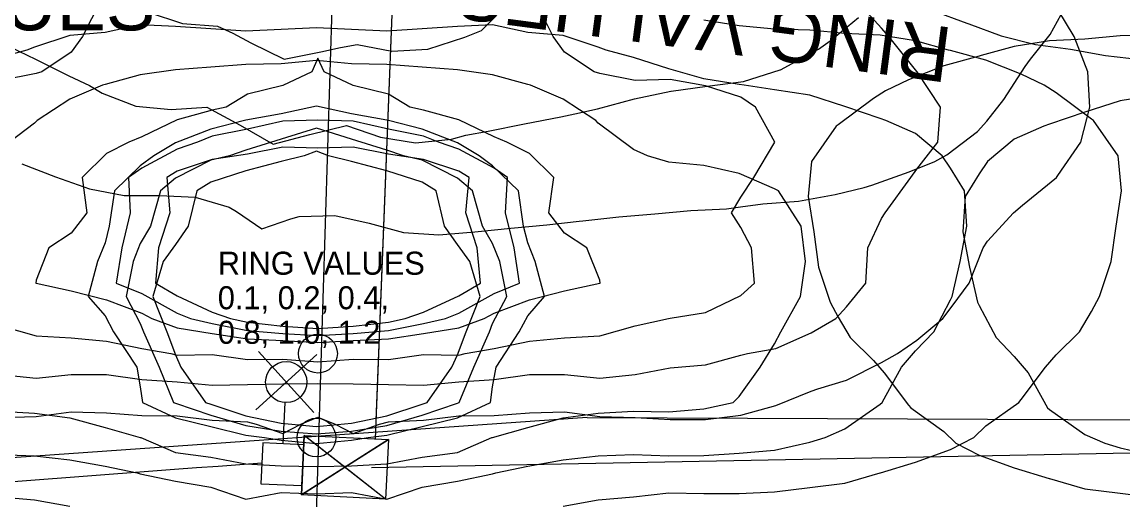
# Model space of a CAD drawing. Extents: x 1638506 to 1658005, y 834807 to 846788.
# Drawn here: x 1642396.4 to 1642635.4, y 842159.5 to 842263.3 of the extents above; entities that cross this region are included whole.
import ezdxf

# ---------------------------------------------------------------- set-up
doc = ezdxf.new("R2010")
doc.units = 0
for name, color, linetype in [('Default', 7, 'Continuous'), ('Old_Level_1', 7, 'Continuous'), ('Old_Level_2', 7, 'Continuous'), ('Scratch_Level_0', 7, 'Continuous')]:
    doc.layers.add(name, color=color, linetype=linetype)

msp = doc.modelspace()

# ---------------------------------------------------------------- linework, layer by layer
at = {"layer": 'Default'}
for p, q in [((1642473.12, 842172.77), (1642480.55, 842360.24)), ((1642473.28, 842176.7), (1642480.22, 842351.8)), ((1642460.38, 842191.09), (1642447.13, 842179.08)), ((1642459.75, 842178.47), (1642447.73, 842191.69)), ((1642453.76, 842185.1), (1642453.76, 842185.1)), ((1642453.12, 842171.7), (1642453.54, 842180.63)), ((1642456.78, 842181.74), (1642456.78, 842181.74)), ((1642475.33, 842159.68), (1642457.68, 842173.5)), ((1642475.95, 842172.63), (1642457.06, 842160.56)), ((1642472.3, 842166.49), (1642741.9, 842171.8))]:
    msp.add_line(p, q, dxfattribs=at)
for points in [[(1642475.33, 842159.68), (1642457.06, 842160.56), (1642457.68, 842173.5), (1642475.95, 842172.63)], [(1642466.5, 842166.59), (1642457.68, 842173.5), (1642457.06, 842160.56)], [(1642457.16, 842162.58), (1642457.58, 842171.48), (1642448.65, 842171.91), (1642448.22, 842163.01)], [(1642466.5, 842166.59), (1642475.95, 842172.63), (1642475.33, 842159.68)]]:
    msp.add_lwpolyline(points, close=True, dxfattribs=at)
msp.add_circle((1642453.75, 842185.07), 4.47, dxfattribs=at)
msp.add_arc((1643863.61, 823017.34), 19202.35, 94.226402, 95.13232, dxfattribs=at)
at = {"layer": 'Old_Level_1'}
for points in [[(1642571.96, 842280.85), (1642572.33, 842280.5), (1642579.46, 842274.19), (1642581.94, 842272.29), (1642586.72, 842269.48), (1642594.08, 842265.78), (1642601.52, 842263.03), (1642601.94, 842262.86), (1642608.96, 842260.27), (1642616.47, 842258.37), (1642624.06, 842257.35), (1642631.62, 842255.97), (1642639.22, 842255.09)], [(1642601.03, 842226.57), (1642598.01, 842231.5), (1642596.16, 842234.22), (1642590.36, 842239.01), (1642583.95, 842241.87), (1642582.71, 842242.29), (1642575.06, 842244.89), (1642567.41, 842247.34), (1642559.76, 842248.56), (1642553.22, 842249.52), (1642552.11, 842249.71), (1642544.46, 842250.88), (1642536.81, 842253.06), (1642529.16, 842255.54), (1642523.23, 842257.17), (1642521.51, 842257.76), (1642513.86, 842260.3), (1642506.21, 842260.98), (1642498.56, 842262.63), (1642490.91, 842262.25), (1642483.26, 842261.74), (1642475.61, 842261.29), (1642467.96, 842261.61), (1642460.31, 842262.01), (1642452.66, 842261.61), (1642445.01, 842261.29), (1642437.36, 842261.74), (1642429.71, 842262.25), (1642422.06, 842262.63), (1642414.41, 842260.98), (1642406.76, 842260.3), (1642399.11, 842257.76), (1642397.4, 842257.17), (1642391.46, 842255.54)], [(1642629.01, 842241.87), (1642628.61, 842242.18), (1642620.96, 842247.85), (1642618.32, 842249.52), (1642613.31, 842251.91), (1642605.66, 842254.95), (1642598.01, 842257.04), (1642597.58, 842257.17), (1642590.36, 842259.14), (1642582.71, 842260.38), (1642575.06, 842260.73), (1642567.41, 842261.46), (1642559.76, 842261.67), (1642552.11, 842262.46), (1642544.46, 842263.68)], [(1642642.45, 842260.45), (1642634.8, 842260.24), (1642627.15, 842259.51), (1642619.5, 842259.16), (1642611.85, 842257.92), (1642604.64, 842255.95), (1642604.2, 842255.82), (1642596.55, 842253.73), (1642588.9, 842250.69), (1642583.89, 842248.3), (1642581.25, 842246.63), (1642573.6, 842240.96), (1642573.2, 842240.65), (1642567.8, 842233), (1642567.06, 842225.35), (1642568.29, 842217.7), (1642569.35, 842210.05), (1642571.85, 842202.4), (1642573.6, 842199.18), (1642576.21, 842194.75), (1642581.25, 842189.77), (1642583.61, 842187.1), (1642588.9, 842180.09), (1642589.41, 842179.45), (1642596.55, 842174.36), (1642599.16, 842171.8), (1642604.2, 842169.17), (1642611.85, 842166.47), (1642619.44, 842164.15), (1642619.5, 842164.13), (1642627.15, 842161.9), (1642634.8, 842160.94), (1642642.45, 842160.02)], [(1642560.63, 842226.57), (1642559.76, 842227.04), (1642552.11, 842230.38), (1642544.46, 842232.1), (1642536.81, 842232.85), (1642532.19, 842234.22), (1642529.16, 842235.55), (1642521.51, 842241.32), (1642520.99, 842241.87), (1642513.86, 842246.51), (1642506.79, 842249.52), (1642506.21, 842249.69), (1642498.56, 842251.82), (1642490.91, 842252.89), (1642483.26, 842253.44), (1642475.61, 842254.02), (1642467.96, 842254.18), (1642460.31, 842254.91), (1642452.66, 842254.18), (1642445.01, 842254.02), (1642437.36, 842253.44), (1642429.71, 842252.89), (1642422.06, 842251.82), (1642414.41, 842249.69), (1642413.84, 842249.52), (1642406.76, 842246.51), (1642399.64, 842241.87), (1642399.11, 842241.32), (1642391.46, 842235.55)], [(1642642.45, 842247.34), (1642634.8, 842246.12), (1642627.15, 842243.67), (1642619.5, 842241.07), (1642618.26, 842240.65), (1642611.85, 842237.79), (1642606.05, 842233), (1642604.2, 842230.28), (1642601.18, 842225.35), (1642600.7, 842217.7), (1642602.14, 842210.05), (1642603.85, 842202.4), (1642604.2, 842201.7), (1642607.88, 842194.75), (1642611.85, 842190.62), (1642614.83, 842187.1), (1642619.04, 842179.45), (1642619.5, 842179.09), (1642627.15, 842173.71), (1642631.48, 842171.8), (1642634.8, 842170.79), (1642642.45, 842169.07)], [(1642507.83, 842211.27), (1642506.21, 842215.27), (1642505.3, 842218.92), (1642504.19, 842226.57), (1642498.56, 842232.02), (1642495.65, 842234.22), (1642490.91, 842237.01), (1642483.26, 842239.96), (1642475.95, 842241.87), (1642475.61, 842241.95), (1642467.96, 842243.3), (1642460.31, 842245.01), (1642452.66, 842243.3), (1642445.01, 842241.95), (1642444.68, 842241.87), (1642437.36, 842239.96), (1642429.71, 842237.01), (1642424.98, 842234.22), (1642422.06, 842232.02), (1642416.44, 842226.57), (1642415.33, 842218.92), (1642414.41, 842215.27), (1642412.79, 842211.27), (1642410.78, 842203.62), (1642414.41, 842199.45), (1642416.28, 842195.97), (1642421.31, 842188.32), (1642422.06, 842184.02), (1642422.51, 842180.67), (1642429.71, 842177.31), (1642437.36, 842175.45), (1642445.01, 842173.54), (1642449.07, 842173.02), (1642452.66, 842172.43), (1642460.31, 842171.75), (1642467.96, 842172.43), (1642471.55, 842173.02), (1642475.61, 842173.54), (1642483.26, 842175.45), (1642490.91, 842177.31), (1642498.12, 842180.67), (1642498.56, 842184.02), (1642499.31, 842188.32), (1642504.34, 842195.97), (1642506.21, 842199.45), (1642509.84, 842203.62), (1642507.83, 842211.27)], [(1642513.86, 842158.12), (1642521.51, 842159.52), (1642529.16, 842160.17), (1642536.81, 842161.01), (1642544.46, 842160.86), (1642552.11, 842160.91), (1642559.76, 842161.24), (1642567.41, 842162.16), (1642575.06, 842163.13), (1642582.71, 842165.36), (1642582.77, 842165.37), (1642590.36, 842167.69), (1642598.01, 842170.4), (1642603.05, 842173.02), (1642605.66, 842175.58), (1642612.81, 842180.67), (1642613.31, 842181.31), (1642618.61, 842188.32), (1642620.96, 842190.99), (1642626.01, 842195.97), (1642628.61, 842200.4), (1642630.36, 842203.62), (1642632.86, 842211.27), (1642633.93, 842218.92), (1642635.15, 842226.57), (1642634.42, 842234.22), (1642629.01, 842241.87)], [(1642500.11, 842211.27), (1642498.56, 842215.14), (1642496.35, 842218.92), (1642494.2, 842226.57), (1642490.91, 842229.35), (1642483.26, 842233.25), (1642479.23, 842234.22), (1642475.61, 842235.42), (1642467.96, 842237.81), (1642460.31, 842240.21), (1642452.66, 842237.81), (1642445.01, 842235.42), (1642441.4, 842234.22), (1642437.36, 842233.25), (1642429.71, 842229.35), (1642426.43, 842226.57), (1642424.27, 842218.92), (1642422.06, 842215.14), (1642420.52, 842211.27), (1642418.98, 842203.62), (1642422.06, 842197.77), (1642422.76, 842195.97), (1642426.14, 842188.32), (1642429.3, 842180.67), (1642429.71, 842180.48), (1642437.36, 842177.87), (1642445.01, 842175.63), (1642452.66, 842174.41), (1642460.31, 842173.81), (1642467.96, 842174.41), (1642475.61, 842175.63), (1642483.26, 842177.87), (1642490.91, 842180.48), (1642491.33, 842180.67), (1642494.48, 842188.32), (1642497.86, 842195.97), (1642498.56, 842197.77), (1642501.65, 842203.62), (1642500.11, 842211.27)], [(1642493.61, 842211.27), (1642490.91, 842214.93), (1642488.14, 842218.92), (1642486.3, 842226.57), (1642483.26, 842228.49), (1642475.61, 842230.95), (1642467.96, 842232.95), (1642462.94, 842234.22), (1642460.31, 842235.18), (1642457.68, 842234.22), (1642452.66, 842232.95), (1642445.01, 842230.95), (1642437.36, 842228.49), (1642434.32, 842226.57), (1642432.49, 842218.92), (1642429.71, 842214.93), (1642427.02, 842211.27), (1642424.78, 842203.62), (1642427.84, 842195.97), (1642429.71, 842190.99), (1642430.9, 842188.32), (1642436.25, 842180.67), (1642437.36, 842180.29), (1642445.01, 842177.72), (1642452.66, 842176.17), (1642460.31, 842175.4), (1642467.96, 842176.17), (1642475.61, 842177.72), (1642483.26, 842180.29), (1642484.38, 842180.67), (1642489.73, 842188.32), (1642490.91, 842190.99), (1642492.79, 842195.97), (1642495.85, 842203.62), (1642493.61, 842211.27)], [(1642391.46, 842169.38), (1642399.11, 842169.08), (1642406.76, 842168.2), (1642414.41, 842166.78), (1642421.36, 842165.37), (1642422.06, 842165.13), (1642429.71, 842163.59), (1642437.36, 842162.24), (1642445.01, 842159.66), (1642452.66, 842161.07), (1642460.31, 842160.78), (1642467.96, 842161.07), (1642475.61, 842159.66), (1642483.26, 842162.24), (1642490.91, 842163.59), (1642498.56, 842165.13), (1642499.27, 842165.37), (1642506.21, 842166.78), (1642513.86, 842168.2), (1642521.51, 842169.08), (1642529.16, 842169.38), (1642536.81, 842169.09), (1642544.46, 842169.1), (1642552.11, 842169.65), (1642559.76, 842170.29), (1642567.41, 842172.01), (1642570.74, 842173.02), (1642575.06, 842174.94), (1642582.71, 842180.31), (1642583.18, 842180.67), (1642587.38, 842188.32), (1642590.36, 842191.85), (1642594.34, 842195.97), (1642598.01, 842202.92), (1642598.36, 842203.62), (1642600.07, 842211.27), (1642601.51, 842218.92), (1642601.03, 842226.57)], [(1642391.46, 842178.77), (1642399.11, 842178.34), (1642406.76, 842177.29), (1642414.41, 842175.24), (1642422.06, 842173.07), (1642422.19, 842173.02), (1642429.71, 842169.8), (1642437.36, 842168.8), (1642445.01, 842167.32), (1642452.66, 842166.91), (1642460.31, 842166.74), (1642467.96, 842166.91), (1642475.61, 842167.32), (1642483.26, 842168.8), (1642490.91, 842169.8), (1642498.43, 842173.02), (1642498.56, 842173.07), (1642506.21, 842175.24), (1642513.86, 842177.29), (1642521.51, 842178.34), (1642529.16, 842178.77), (1642536.81, 842178.63), (1642544.46, 842179.26), (1642550.77, 842180.67), (1642552.11, 842181.95), (1642556.66, 842188.32), (1642559.76, 842193.38), (1642561.13, 842195.97), (1642565.42, 842203.62), (1642566.48, 842211.27), (1642565.56, 842218.92), (1642560.63, 842226.57)], [(1642391.46, 842160.17), (1642399.11, 842159.52), (1642406.76, 842158.12)]]:
    msp.add_lwpolyline(points, dxfattribs=at)
msp.add_circle((1642460.31, 842173.02), 4.21, dxfattribs=at)
at = {"layer": 'Old_Level_2'}
for p, q in [((1642458.82, 842108.44), (1642469.85, 842461.62)), ((1642519.11, 842177.39), (1642217.73, 842156.22)), ((1642519.08, 842177.38), (1642658.6, 842176.81))]:
    msp.add_line(p, q, dxfattribs=at)
at = {"layer": 'Scratch_Level_0'}
for points in [[(1642413.4, 842267.75), (1642409.54, 842260.1), (1642407.09, 842256.7), (1642400.66, 842252.45), (1642399.44, 842252.07), (1642391.79, 842250.56)], [(1642396.33, 842232.45), (1642403.67, 842229.66), (1642411.05, 842227.06), (1642418.57, 842225.57), (1642426.28, 842225.56), (1642433.96, 842225.25), (1642441.38, 842223.04), (1642442.96, 842222.11), (1642448.48, 842218.38), (1642454.78, 842220.55), (1642456.55, 842221.04), (1642464.29, 842221.25), (1642471.79, 842219.57), (1642479.24, 842217.57), (1642486.89, 842217.07), (1642494.69, 842217.67), (1642502.51, 842218.46), (1642510.32, 842219.2), (1642517.34, 842220.03), (1642518.16, 842220.11), (1642525.98, 842220.94), (1642533.79, 842221.62), (1642541.59, 842222.3), (1642549.36, 842222.71), (1642552.41, 842223.12), (1642557.22, 842223.76), (1642565.02, 842224.38), (1642572.92, 842225.83), (1642579.24, 842227.3), (1642580.91, 842227.85), (1642589, 842230.72), (1642594.57, 842233), (1642597.2, 842234.41), (1642603.86, 842239.49), (1642605.89, 842241.76), (1642609.6, 842246.45), (1642614.17, 842253.56), (1642615.37, 842255.2), (1642619.64, 842260.56), (1642623.63, 842267.75)], [(1642555.62, 842244.8), (1642552.44, 842246.95), (1642544.79, 842249.42), (1642537.14, 842250.78), (1642529.49, 842250.56), (1642521.84, 842252.07), (1642520.62, 842252.45), (1642514.19, 842256.7), (1642511.74, 842260.1), (1642507.88, 842267.75)], [(1642590.75, 842252.45), (1642590.69, 842252.53), (1642584.57, 842260.1), (1642583.04, 842261.93), (1642577.64, 842267.75)], [(1642392.06, 842258.65), (1642399.32, 842255.16), (1642406.56, 842251.55), (1642411.02, 842249.47), (1642413.78, 842247.77), (1642421.13, 842244.99), (1642428.75, 842244.27), (1642436.53, 842244.8), (1642443.73, 842240.84), (1642450.9, 842236.7), (1642458.9, 842238.84), (1642466.87, 842240.8), (1642474.25, 842238.27), (1642481.8, 842236.99), (1642489.62, 842237.78), (1642492.72, 842238.7), (1642497.57, 842239.55), (1642505.5, 842241.17), (1642513.41, 842242.66), (1642516.42, 842243.29), (1642521.36, 842244.39), (1642529.36, 842246.59), (1642537.3, 842248.25), (1642537.33, 842248.26), (1642545.16, 842249.33), (1642553.01, 842250.37), (1642561.02, 842252.85), (1642561.05, 842252.87), (1642569.36, 842257.33), (1642571.87, 842259.14), (1642577.98, 842264.21)], [(1642423.81, 842265.36), (1642431.21, 842262.95), (1642438.85, 842262.35), (1642442.17, 842260.8), (1642446.09, 842258.75), (1642453.33, 842255.18), (1642461.26, 842256.76), (1642465.57, 842257.71), (1642469.18, 842258.35), (1642476.71, 842256.95), (1642484.49, 842257.37), (1642492.55, 842259.99), (1642496.16, 842261.4), (1642501.1, 842266.37)], [(1642624.81, 842260.1), (1642621.29, 842265.98)], [(1642391.79, 842177.35), (1642399.44, 842177.6), (1642407.09, 842178.59), (1642414.74, 842178.38), (1642422.39, 842177.83), (1642430.04, 842177.75), (1642437.69, 842176.79), (1642445.34, 842176.41), (1642447.26, 842175.95), (1642452.99, 842173.9), (1642456.9, 842175.95), (1642460.64, 842177.43), (1642464.37, 842175.95), (1642468.29, 842173.9), (1642474.01, 842175.95), (1642475.94, 842176.41), (1642483.59, 842176.79), (1642491.24, 842177.75), (1642498.89, 842177.83), (1642506.54, 842178.38), (1642514.19, 842178.59), (1642521.84, 842177.6), (1642529.49, 842177.35), (1642537.14, 842176.95), (1642544.79, 842176.95), (1642552.44, 842177.92), (1642560.09, 842180.01), (1642567.74, 842183.08), (1642569.15, 842183.6), (1642575.39, 842185.5), (1642583.04, 842189.34), (1642586.45, 842191.25), (1642590.69, 842194.15), (1642596.29, 842198.9), (1642598.34, 842201.58), (1642602.05, 842206.55), (1642605.1, 842214.2), (1642605.99, 842215.65), (1642611.64, 842221.85), (1642613.64, 842223.52), (1642621, 842229.5), (1642621.29, 842229.93), (1642626.32, 842237.15), (1642628.22, 842244.8), (1642627.83, 842252.45), (1642624.81, 842260.1)], [(1642521.92, 842206.55), (1642521.84, 842207.21), (1642519.05, 842214.2), (1642514.19, 842217.39), (1642510.8, 842221.85), (1642511.84, 842229.5), (1642506.54, 842234.69), (1642501.67, 842237.15), (1642498.89, 842238.33), (1642491.24, 842241.98), (1642483.59, 842244.1), (1642480.58, 842244.8), (1642475.94, 842247.61), (1642468.29, 842249.47), (1642461.97, 842252.45), (1642460.64, 842255.38), (1642459.31, 842252.45), (1642452.99, 842249.47), (1642445.34, 842247.61), (1642440.69, 842244.8), (1642437.69, 842244.1), (1642430.04, 842241.98), (1642422.39, 842238.33), (1642419.6, 842237.15), (1642414.74, 842234.69), (1642409.44, 842229.5), (1642410.48, 842221.85), (1642407.09, 842217.39), (1642402.22, 842214.2), (1642399.44, 842207.2), (1642399.35, 842206.55), (1642399.44, 842206.52), (1642407.09, 842204.85), (1642414.74, 842202.95), (1642422.39, 842200.06), (1642424.55, 842198.9), (1642430.04, 842196.88), (1642437.69, 842195.59), (1642445.34, 842194.46), (1642452.99, 842194.07), (1642460.64, 842193.7), (1642468.29, 842194.07), (1642475.94, 842194.46), (1642483.59, 842195.59), (1642491.24, 842196.88), (1642496.72, 842198.9), (1642498.89, 842200.06), (1642506.54, 842202.95), (1642514.19, 842204.85), (1642521.84, 842206.52), (1642521.92, 842206.55)], [(1642391.79, 842186.68), (1642399.44, 842185.94), (1642407.09, 842186.7), (1642414.74, 842186.71), (1642422.39, 842185.6), (1642430.04, 842185.13), (1642437.69, 842184.39), (1642445.34, 842184.51), (1642452.99, 842184.71), (1642460.64, 842184.78), (1642468.29, 842184.71), (1642475.94, 842184.51), (1642483.59, 842184.39), (1642491.24, 842185.13), (1642498.89, 842185.6), (1642506.54, 842186.71), (1642514.19, 842186.7), (1642521.84, 842185.94), (1642529.49, 842186.68), (1642537.14, 842188.14), (1642544.79, 842188.81), (1642552.44, 842190.89), (1642553.89, 842191.25), (1642560.09, 842192.35), (1642567.74, 842195.77), (1642573.06, 842198.9), (1642575.39, 842201.44), (1642579.57, 842206.55), (1642580.04, 842214.2), (1642583.04, 842220.59), (1642583.8, 842221.85), (1642589.38, 842229.5), (1642590.69, 842231.31), (1642595.22, 842237.15), (1642595.82, 842244.8), (1642590.75, 842252.45)], [(1642391.79, 842197.26), (1642399.44, 842195.09), (1642407.09, 842194.7), (1642414.74, 842193.92), (1642422.39, 842192.33), (1642428.68, 842191.25), (1642430.04, 842190.9), (1642437.69, 842191.05), (1642445.34, 842189.99), (1642452.99, 842190.04), (1642460.64, 842189.49), (1642468.29, 842190.04), (1642475.94, 842189.99), (1642483.59, 842191.05), (1642491.24, 842190.9), (1642492.6, 842191.25), (1642498.89, 842192.33), (1642506.54, 842193.92), (1642514.19, 842194.7), (1642521.84, 842195.09), (1642529.49, 842197.26), (1642536.78, 842198.9), (1642537.14, 842198.97), (1642544.79, 842200.18), (1642552.44, 842203.87), (1642555.45, 842206.55), (1642554.81, 842214.2), (1642552.44, 842218.63), (1642550.47, 842221.85), (1642552.44, 842225.23), (1642555.3, 842229.5), (1642559.83, 842237.15), (1642555.62, 842244.8)], [(1642501.79, 842229.5), (1642498.89, 842231.5), (1642491.24, 842235.61), (1642486.78, 842237.15), (1642483.59, 842238.46), (1642475.94, 842240.02), (1642468.29, 842241.72), (1642460.64, 842241.92), (1642452.99, 842241.72), (1642445.34, 842240.02), (1642437.69, 842238.46), (1642434.5, 842237.15), (1642430.04, 842235.61), (1642422.39, 842231.5), (1642419.48, 842229.5), (1642419.9, 842221.85), (1642418.04, 842214.2), (1642416.84, 842206.55), (1642422.39, 842204.28), (1642430.04, 842200.05), (1642432.94, 842198.9), (1642437.69, 842197.8), (1642445.34, 842196.27), (1642452.99, 842195.65), (1642460.64, 842195.2), (1642468.29, 842195.65), (1642475.94, 842196.27), (1642483.59, 842197.8), (1642488.34, 842198.9), (1642491.24, 842200.05), (1642498.89, 842204.28), (1642504.43, 842206.55), (1642503.23, 842214.2), (1642501.37, 842221.85), (1642501.79, 842229.5)], [(1642493.44, 842229.5), (1642491.24, 842230.84), (1642483.59, 842233.42), (1642475.94, 842234.53), (1642468.29, 842236.05), (1642460.64, 842235.85), (1642452.99, 842236.05), (1642445.34, 842234.53), (1642437.69, 842233.42), (1642430.04, 842230.84), (1642427.83, 842229.5), (1642428.5, 842221.85), (1642426.04, 842214.2), (1642425.36, 842206.55), (1642430.04, 842203.82), (1642437.69, 842200.25), (1642441.68, 842198.9), (1642445.34, 842198.08), (1642452.99, 842197.24), (1642460.64, 842196.7), (1642468.29, 842197.24), (1642475.94, 842198.08), (1642479.59, 842198.9), (1642483.59, 842200.25), (1642491.24, 842203.82), (1642495.91, 842206.55), (1642495.23, 842214.2), (1642492.77, 842221.85), (1642493.44, 842229.5)]]:
    msp.add_lwpolyline(points, dxfattribs=at)
msp.add_circle((1642460.64, 842191.25), 4.21, dxfattribs=at)

# ---------------------------------------------------------------- texts
at = {"layer": 'Old_Level_1'}
for s, p in [('RING VALUES', (1642438.89, 842208.38)), ('0.1, 0.2, 0.4,', (1642438.89, 842200.88)), ('0.8, 1.0, 1.2', (1642438.89, 842193.38))]:
    msp.add_text(s, height=5, dxfattribs=at).set_placement(p)
at = {"layer": 'Scratch_Level_0'}
msp.add_text('RING VALUES', height=12, rotation=172.4934, dxfattribs=at).set_placement((1642598.7, 842261.96))
msp.add_text('RING VALUES', height=12, dxfattribs=at).set_placement((1642317.41, 842261.45))

doc.saveas('drawing.dxf')
